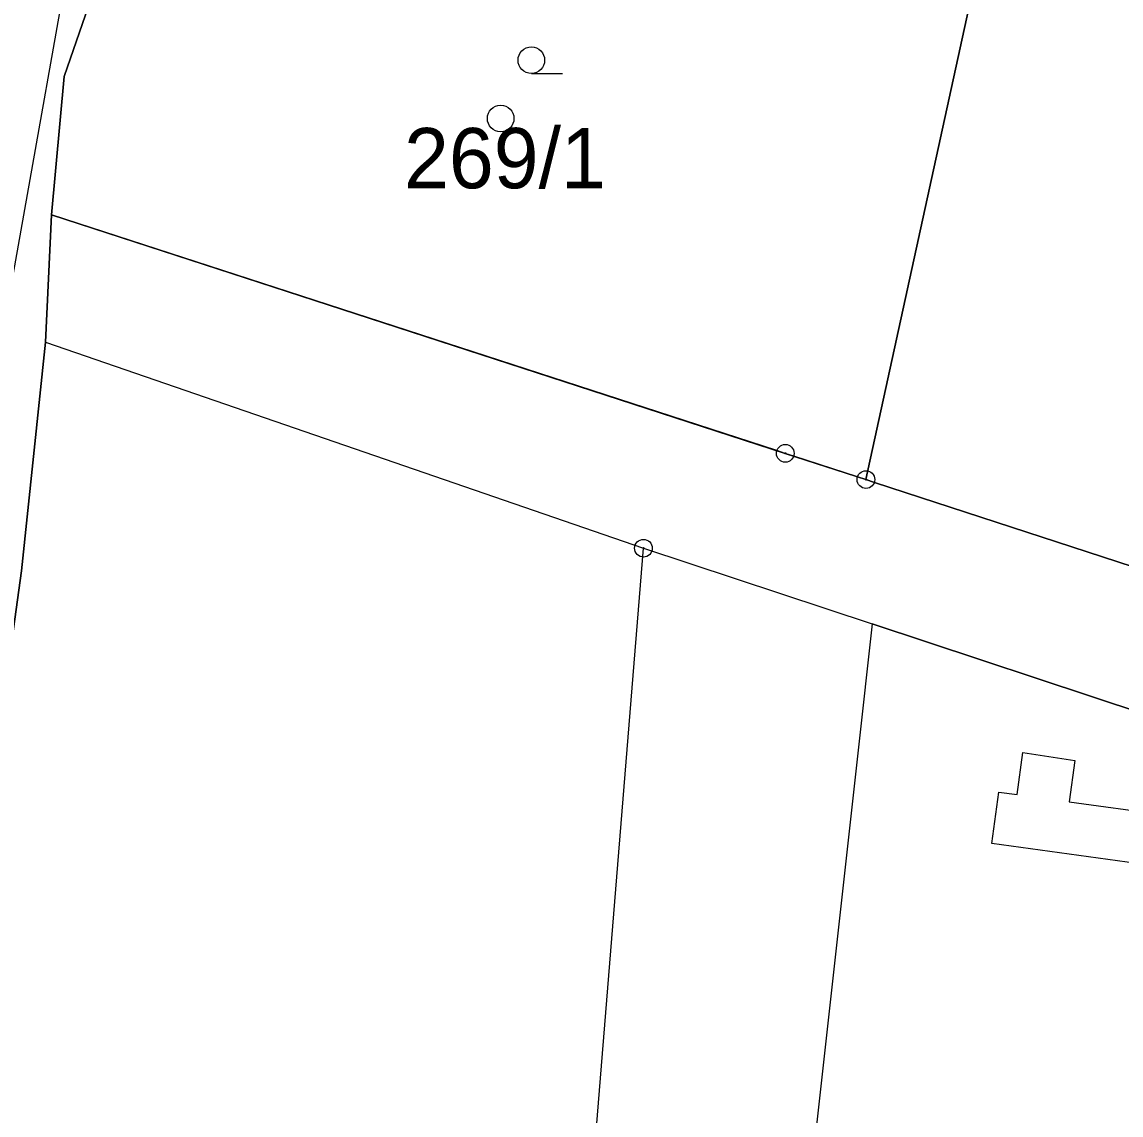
# Model space of a CAD drawing. Extents: x -537341 to -532984, y -1143469 to -1141314.
# Drawn here: x -534544.9 to -534482.9, y -1143022.1 to -1142960.5 of the extents above; entities that cross this region are included whole.
import ezdxf

# ---------------------------------------------------------------- set-up
doc = ezdxf.new("R2010")
doc.units = 0
for name, color, linetype in [('Hranice parcel', 7, 'Continuous'), ('parcelní_č_2000', 7, 'Continuous'), ('u_obec_Horní_Moš', 7, 'Continuous'), ('u_pricne', 7, 'Continuous'), ('U_SOUKROMÉ', 7, 'Continuous'), ('u_ŘSD', 7, 'Continuous'), ('Značky bodu BP', 7, 'Continuous'), ('Značky kultur', 7, 'Continuous')]:
    doc.layers.add(name, color=color, linetype=linetype)

msp = doc.modelspace()

# ---------------------------------------------------------------- linework, layer by layer
at = {"layer": 'Hranice parcel'}
for p, q in [((-534490.47, -1142955.17), (-534497.26, -1142986.3)), ((-534543.19, -1142971.37), (-534543.53, -1142978.55)), ((-534543.53, -1142978.55), (-534509.81, -1142990.17)), ((-534497.26, -1142986.3), (-534397.75, -1143018.75)), ((-534525.46, -1143182.66), (-534509.81, -1142990.17)), ((-534509.81, -1142990.17), (-534496.91, -1142994.44)), ((-534439.99, -1143013.28), (-534496.91, -1142994.44))]:
    msp.add_line(p, q, dxfattribs=at)
for points in [[(-534539.53, -1142955), (-534542.49, -1142963.57), (-534543.19, -1142971.37)], [(-534543.19, -1142971.37), (-534501.81, -1142984.82), (-534497.26, -1142986.3)], [(-534543.53, -1142978.55), (-534544.88, -1142991.45), (-534549.21, -1143022.63), (-534552.02, -1143047.59), (-534553.94, -1143062.92), (-534556.87, -1143095.87), (-534559.56, -1143122.71), (-534561.15, -1143142.68), (-534562.36, -1143169.1), (-534564.99, -1143179.68)], [(-534496.91, -1142994.44), (-534497.7, -1143001.56), (-534503.19, -1143050.98), (-534456.23, -1143061.74)], [(-534477.1, -1143011.6), (-534480.51, -1143010.58), (-534479.87, -1143008.42), (-534480.9, -1143008.1), (-534490.17, -1143006.83), (-534489.77, -1143003.93), (-534488.74, -1143004.07), (-534488.41, -1143001.69), (-534485.48, -1143002.14), (-534485.8, -1143004.47), (-534480.56, -1143005.19), (-534475.61, -1143006.71)]]:
    msp.add_lwpolyline(points, dxfattribs=at)
at = {"layer": 'u_obec_Horní_Moš'}
for p, q in [((-534543.19, -1142971.37), (-534543.53, -1142978.55)), ((-534543.53, -1142978.55), (-534509.81, -1142990.17)), ((-534497.736, -1142986.145), (-534501.335, -1142984.975)), ((-534497.26, -1142986.3), (-534497.736, -1142986.145)), ((-534496.785, -1142986.455), (-534497.26, -1142986.3)), ((-534509.81, -1142990.17), (-534496.91, -1142994.44)), ((-534496.91, -1142994.44), (-534439.99, -1143013.28))]:
    msp.add_line(p, q, dxfattribs=at)
for points in [[(-534501.335, -1142984.975), (-534501.81, -1142984.82), (-534502.286, -1142984.665), (-534543.19, -1142971.37)], [(-534397.75, -1143018.75), (-534398.225, -1143018.595), (-534496.785, -1142986.455)]]:
    msp.add_lwpolyline(points, dxfattribs=at)
at = {"layer": 'u_pricne'}
msp.add_line((-534533.254, -1142906.523), (-534552.634, -1143015.552), dxfattribs=at)
at = {"layer": 'U_SOUKROMÉ'}
for p, q in [((-534539.53, -1142955), (-534542.49, -1142963.57)), ((-534497.26, -1142986.3), (-534490.47, -1142955.17)), ((-534490.47, -1142955.17), (-534497.26, -1142986.3)), ((-534542.49, -1142963.57), (-534543.19, -1142971.37)), ((-534501.81, -1142984.82), (-534501.335, -1142984.975)), ((-534497.26, -1142986.3), (-534496.785, -1142986.455))]:
    msp.add_line(p, q, dxfattribs=at)
for points in [[(-534517.863, -1142966.68), (-534517.863, -1142966.68), (-534517.863, -1142966.68)], [(-534543.19, -1142971.37), (-534502.286, -1142984.665), (-534501.81, -1142984.82)], [(-534501.335, -1142984.975), (-534497.736, -1142986.145), (-534497.26, -1142986.3)], [(-534496.785, -1142986.455), (-534398.225, -1143018.595), (-534397.75, -1143018.75)]]:
    msp.add_lwpolyline(points, dxfattribs=at)
msp.add_circle((-534517.863, -1142965.93), 0.75, dxfattribs=at)
msp.add_circle((-534517.863, -1142965.93), 0.75, dxfattribs=at)
at = {"layer": 'u_ŘSD'}
for p, q in [((-534542.49, -1142963.57), (-534539.53, -1142955)), ((-534543.19, -1142971.37), (-534542.49, -1142963.57)), ((-534543.53, -1142978.55), (-534543.19, -1142971.37))]:
    msp.add_line(p, q, dxfattribs=at)
msp.add_lwpolyline([(-534564.99, -1143179.68), (-534562.36, -1143169.1), (-534561.15, -1143142.68), (-534559.56, -1143122.71), (-534556.87, -1143095.87), (-534553.94, -1143062.92), (-534552.02, -1143047.59), (-534549.21, -1143022.63), (-534544.88, -1142991.45), (-534543.53, -1142978.55)], dxfattribs=at)
at = {"layer": 'Značky bodu BP'}
for centre, radius in [((-534501.81, -1142984.82), 0.5), ((-534501.81, -1142984.82), 0.0303), ((-534497.26, -1142986.3), 0.5), ((-534497.26, -1142986.3), 0.0303), ((-534509.81, -1142990.17), 0.5), ((-534509.81, -1142990.17), 0.0303)]:
    msp.add_circle(centre, radius, dxfattribs=at)
at = {"layer": 'Značky kultur'}
msp.add_line((-534516.133, -1142963.397), (-534514.383, -1142963.397), dxfattribs=at)
msp.add_circle((-534516.133, -1142962.646), 0.75, dxfattribs=at)

# ---------------------------------------------------------------- texts
at = {"layer": 'parcelní_č_2000'}
msp.add_text('269/1', height=3.4, dxfattribs=at).set_placement((-534523.312, -1142969.87))

doc.saveas('drawing.dxf')
